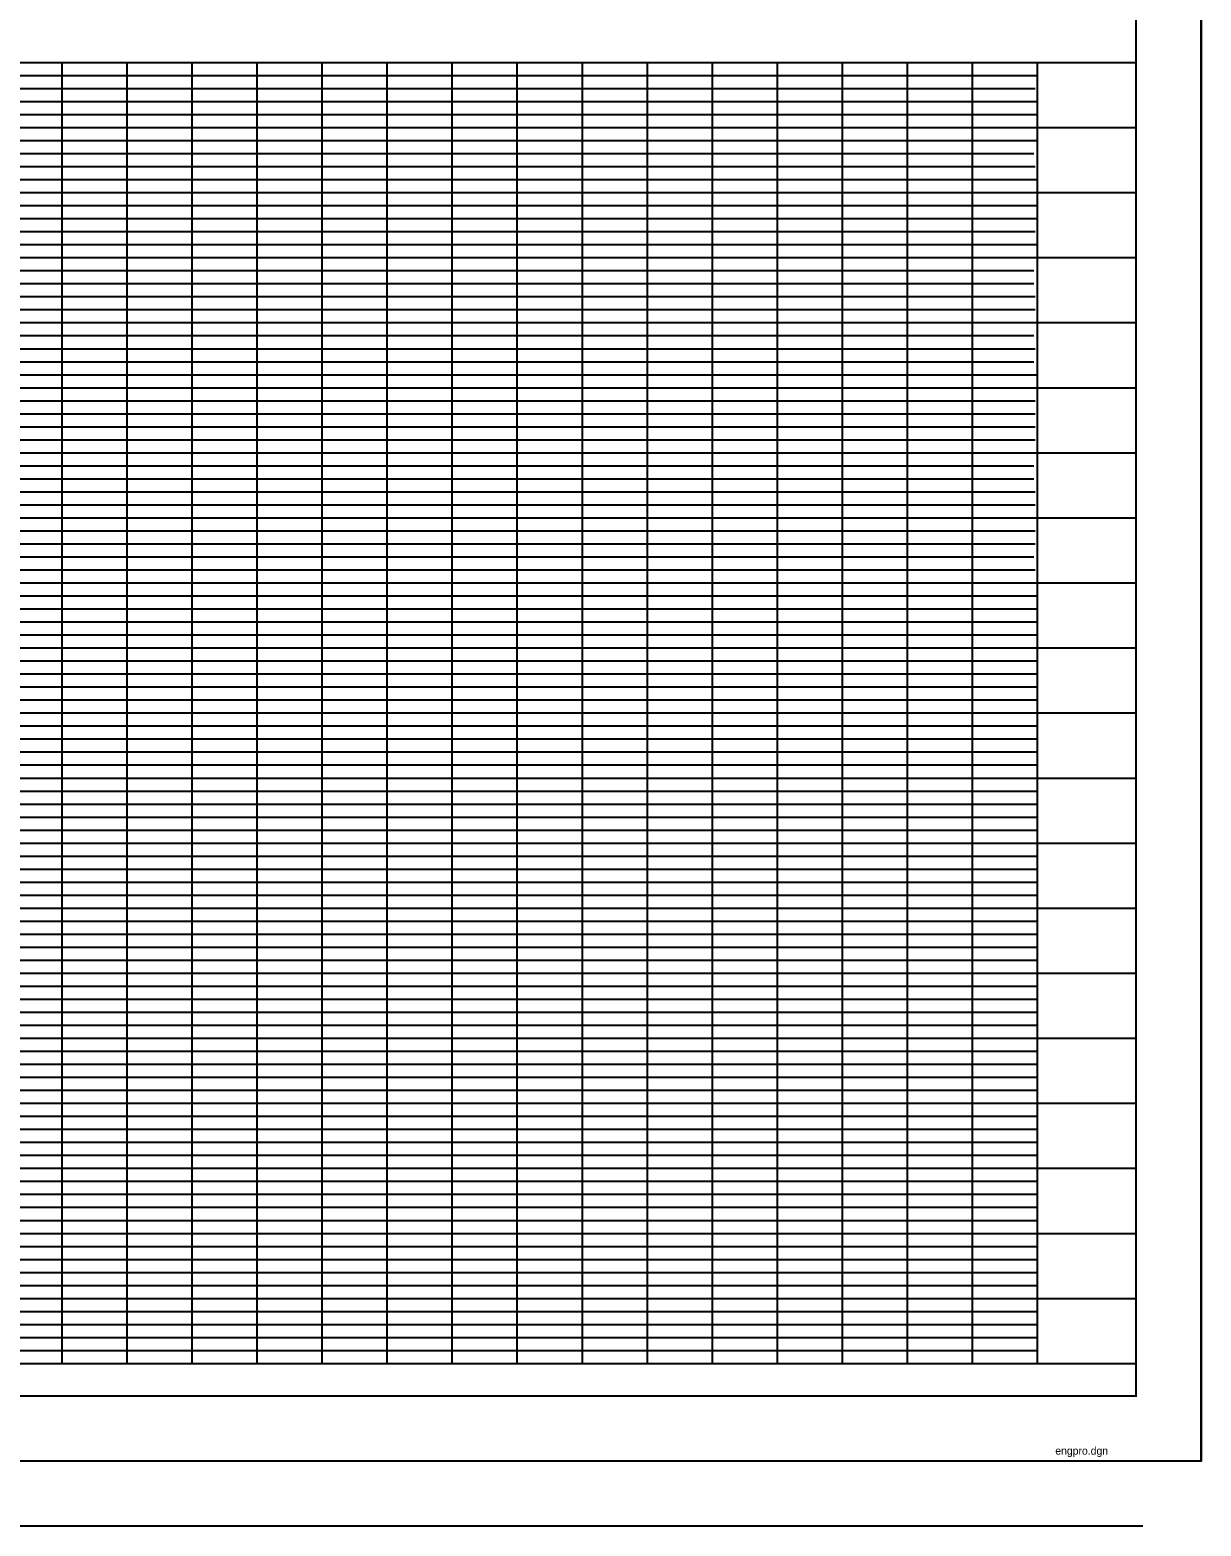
# Model space of a CAD drawing. Extents: x -184 to 1613, y -562 to 587.
# Drawn here: x 1163 to 1613, y -562 to 12 of the extents above; entities that cross this region are included whole.
import ezdxf

# ---------------------------------------------------------------- set-up
doc = ezdxf.new("R2010")
doc.units = 0
for name, color, linetype in [('Level 1', 7, 'Continuous'), ('Level 2', 7, 'Continuous'), ('Level 3', 7, 'Continuous'), ('Level 50', 7, 'Continuous')]:
    doc.layers.add(name, color=color, linetype=linetype)

msp = doc.modelspace()

# ---------------------------------------------------------------- linework, layer by layer
at = {"layer": 'Level 1'}
for p, q in [((1613, -537.5), (1613, 562.5)), ((1588, -512.5), (1588, 537.55)), ((-87.5, 0), (1588.35, 0)), ((1175, 0), (1175, -500)), ((1225, 0), (1225, -500)), ((1275, 0), (1275, -500)), ((1325, 0), (1325, -500)), ((1375, 0), (1375, -500)), ((1425, 0), (1425, -500)), ((1475, 0), (1475, -500)), ((1525, 0), (1525, -500)), ((1550, 0), (1550, -500)), ((-49.95, -5), (1549.8, -5)), ((-49.95, -10), (1549.25, -10)), ((-49.95, -15), (1549.8, -15)), ((-49.9, -20), (1549.8, -20)), ((-49.95, -30), (1549.8, -30)), ((-49.95, -35), (1548.75, -35)), ((-49.95, -40), (1549.25, -40)), ((-49.95, -45), (1549.8, -45)), ((-49.95, -55), (1549.8, -55)), ((-49.95, -60), (1549.8, -60)), ((-49.95, -65), (1549.25, -65)), ((-49.95, -70), (1549.8, -70)), ((-49.95, -80), (1548.75, -80)), ((-49.95, -85), (1548.75, -85)), ((-49.95, -90), (1549.25, -90)), ((-49.95, -95), (1549.25, -95)), ((-49.95, -105), (1548.75, -105)), ((-49.95, -110), (1549.25, -110)), ((-49.95, -115), (1548.75, -115)), ((-49.9, -120), (1549.8, -120)), ((-49.95, -130), (1549.25, -130)), ((-49.95, -135), (1549.25, -135)), ((-49.95, -140), (1549.25, -140)), ((-49.95, -145), (1549.25, -145)), ((-49.85, -155), (1548.75, -155)), ((-49.85, -160), (1548.75, -160)), ((-49.9, -165), (1549.25, -165)), ((-49.9, -170), (1549.25, -170)), ((-49.95, -180), (1549.25, -180)), ((-49.95, -185), (1549.25, -185)), ((-49.95, -190), (1548.75, -190)), ((-49.95, -195), (1549.25, -195)), ((-49.95, -195), (1549.25, -195)), ((-49.95, -195), (1548.75, -195)), ((-49.95, -205), (1549.8, -205)), ((-49.95, -210), (1549.8, -210)), ((-49.95, -215), (1549.8, -215)), ((-49.95, -220), (1549.8, -220)), ((-49.95, -230), (1549.8, -230)), ((-49.95, -235), (1549.8, -235)), ((-49.95, -240), (1549.8, -240)), ((-49.95, -245), (1549.8, -245)), ((-49.95, -255), (1549.85, -255)), ((-49.95, -260), (1549.85, -260)), ((-49.95, -265), (1549.85, -265)), ((-49.95, -270), (1549.85, -270)), ((-49.95, -280), (1549.85, -280)), ((-49.95, -285), (1549.85, -285)), ((-49.95, -290), (1549.85, -290)), ((-49.95, -295), (1549.85, -295)), ((-49.95, -305), (1549.85, -305)), ((-49.95, -310), (1549.85, -310)), ((-49.95, -315), (1549.85, -315)), ((-49.95, -320), (1549.85, -320)), ((-49.95, -330), (1549.85, -330)), ((-49.9, -330), (1549.85, -330)), ((-49.95, -335), (1549.85, -335)), ((-49.9, -340), (1549.6, -340)), ((-49.9, -345), (1549.6, -345)), ((-49.9, -355), (1549.8, -355)), ((-49.95, -360), (1549.95, -360)), ((-49.95, -365), (1549.95, -365)), ((-49.9, -370), (1549.95, -370)), ((-49.95, -380), (1549.95, -380)), ((-49.95, -385), (1549.95, -385)), ((-49.95, -390), (1549.95, -390)), ((-49.9, -395), (1549.95, -395)), ((-49.95, -405), (1549.95, -405)), ((-49.95, -410), (1549.95, -410)), ((-49.95, -415), (1549.95, -415)), ((-49.95, -420), (1549.85, -420)), ((-49.9, -430), (1549.6, -430)), ((-49.95, -435), (1549.85, -435)), ((-49.95, -440), (1549.85, -440)), ((-49.95, -445), (1549.85, -445)), ((-49.85, -455), (1549.85, -455)), ((-49.95, -460), (1549.85, -460)), ((-49.95, -465), (1549.85, -465)), ((-49.95, -470), (1549.85, -470)), ((-49.85, -480), (1549.85, -480)), ((-49.85, -485), (1549.85, -485)), ((-49.85, -490), (1549.85, -490)), ((-87.5, -500), (1588.35, -500)), ((-87.5, -500), (1588.35, -500)), ((-49.85, -495), (1549.85, -495)), ((-87.5, -512.5), (1588.35, -512.5)), ((1590.65, -537.5), (-169.35, -537.5)), ((1590.65, -562.5), (-169.35, -562.5))]:
    msp.add_line(p, q, dxfattribs=at)
at = {"layer": 'Level 2'}
for p, q in [((-87.5, -25), (1588.35, -25)), ((-87.5, -75), (1588.35, -75)), ((-87.5, -125), (1588.35, -125)), ((-87.5, -175), (1588.35, -175)), ((-87.35, -175), (1588.35, -175)), ((-87.5, -225), (1588.35, -225)), ((-87.5, -275), (1588.35, -275)), ((-87.5, -325), (1588.35, -325)), ((-87.5, -375), (1588.35, -375)), ((-87.5, -425), (1588.35, -425)), ((-87.5, -475), (1588.35, -475))]:
    msp.add_line(p, q, dxfattribs=at)
at = {"layer": 'Level 3'}
for p, q in [((1200, 0), (1200, -500)), ((1250, 0), (1250, -500)), ((1300, 0), (1300, -500)), ((1350, 0), (1350, -500)), ((1400, 0), (1400, -500)), ((1450, 0), (1450, -500)), ((1500, 0), (1500, -500)), ((-87.5, -50), (1588.35, -50)), ((-87.5, -100), (1588.35, -100)), ((-87.5, -150), (1588.35, -150)), ((-87.5, -200), (1588.35, -200)), ((-87.5, -250), (1588.35, -250)), ((-87.5, -300), (1588.35, -300)), ((-87.5, -350), (1588.35, -350)), ((-87.5, -400), (1588.35, -400)), ((-87.5, -450), (1588.35, -450))]:
    msp.add_line(p, q, dxfattribs=at)
at = {"layer": 'Level 50'}
msp.add_lwpolyline([(-182.9, 562.5), (1613, 562.5), (1613, -537.5), (-182.9, -537.5)], close=True, dxfattribs=at)

# ---------------------------------------------------------------- texts
at = {"layer": 'Level 1'}
msp.add_text('engpro.dgn', height=3, dxfattribs=at).set_placement((1556.95, -535.05))

doc.saveas('drawing.dxf')
